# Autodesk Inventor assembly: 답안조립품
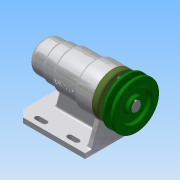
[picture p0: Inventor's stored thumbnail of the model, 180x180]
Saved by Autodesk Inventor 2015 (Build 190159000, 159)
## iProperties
Created: 2017-09
Part Number: 답안조립품
Document SubType Name: Assembly
Designer: Administrator
Author: Administrator
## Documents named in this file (11)
- C:\Users\Administrator\Desktop\470907V1008\답안조립품.iam
- C:\Users\Administrator\Desktop\470907V1008\본체.ipt
- C:\Users\Administrator\Desktop\470907V1008\커버.ipt
- C:\Users\Administrator\Desktop\470907V1008\축.ipt
- C:\Users\Administrator\Desktop\470907V1008\베어링 6004.ipt
- C:\Users\Administrator\Desktop\470907V1008\어댑터슬리브.ipt
- C:\Users\Administrator\Desktop\470907V1008\베어링 51202.ipt
- C:\Users\Administrator\Desktop\470907V1008\키 5 x 5 x 16.ipt
- C:\Users\Administrator\Desktop\470907V1008\V벨트풀리.ipt
- C:\Users\Administrator\Desktop\470907V1008\멈춤나사 M3x8.ipt
- C:\Users\Administrator\Desktop\470907V1008\볼트 M4 x 12.ipt
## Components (1 placed, 1 different names)
1. V벨트풀리:1
